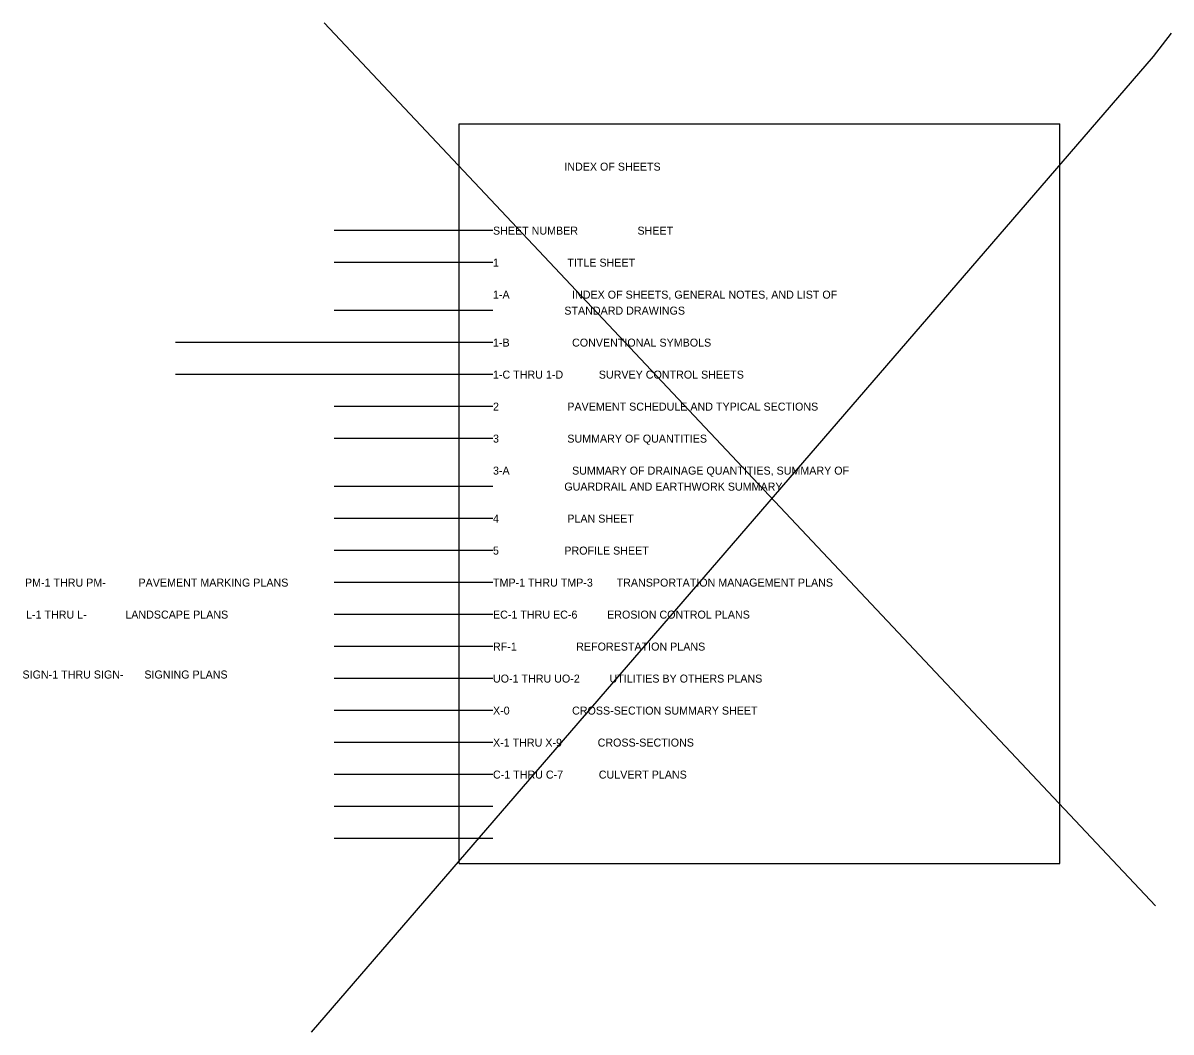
# Model space of a CAD drawing. Extents: x 573885.1 to 573944.9, y -53259.7 to -53181.6.
# Drawn here: x 573885.07 to 573899.41, y -53198.45 to -53185.84 of the extents above; entities that cross this region are included whole.
import ezdxf

# ---------------------------------------------------------------- set-up
doc = ezdxf.new("R2010")
doc.units = 0
for name, color, linetype in [('Scratch_Level_0', 7, 'Continuous'), ('Sheet Data Text CELL', 7, 'Continuous'), ('Sheet Summary Combination Grid CELL', 7, 'Continuous')]:
    doc.layers.add(name, color=color, linetype=linetype)

msp = doc.modelspace()

# ---------------------------------------------------------------- linework, layer by layer
at = {"layer": 'Scratch_Level_0'}
for p, q in [((573890.94, -53188.434), (573888.957, -53188.434)), ((573890.94, -53188.834), (573888.957, -53188.834)), ((573890.94, -53189.434), (573888.957, -53189.434)), ((573888.957, -53189.834), (573886.973, -53189.834)), ((573890.94, -53189.834), (573888.957, -53189.834)), ((573888.957, -53190.234), (573886.973, -53190.234)), ((573888.957, -53190.234), (573886.973, -53190.234)), ((573890.94, -53190.234), (573888.957, -53190.234)), ((573890.94, -53190.234), (573888.957, -53190.234)), ((573890.94, -53190.634), (573888.957, -53190.634)), ((573890.94, -53191.034), (573888.957, -53191.034)), ((573890.94, -53191.634), (573888.957, -53191.634)), ((573890.94, -53191.634), (573888.957, -53191.634)), ((573890.94, -53192.034), (573888.957, -53192.034)), ((573890.94, -53192.434), (573888.957, -53192.434)), ((573890.94, -53192.834), (573888.957, -53192.834)), ((573890.94, -53193.234), (573888.957, -53193.234)), ((573890.94, -53193.634), (573888.957, -53193.634)), ((573890.94, -53194.034), (573888.957, -53194.034)), ((573890.94, -53194.434), (573888.957, -53194.434)), ((573890.94, -53194.834), (573888.957, -53194.834)), ((573890.94, -53195.234), (573888.957, -53195.234)), ((573890.94, -53195.634), (573888.957, -53195.634)), ((573890.94, -53196.034), (573888.957, -53196.034))]:
    msp.add_line(p, q, dxfattribs=at)
at = {"layer": 'Sheet Data Text CELL'}
for p, q in [((573890.518, -53196.344), (573890.518, -53187.099)), ((573890.518, -53187.099), (573898.025, -53187.099)), ((573898.025, -53196.344), (573898.025, -53187.099)), ((573890.518, -53196.344), (573898.025, -53196.344))]:
    msp.add_line(p, q, dxfattribs=at)
at = {"layer": 'Sheet Summary Combination Grid CELL'}
for p, q in [((573888.83, -53185.838), (573899.221, -53196.876)), ((573899.414, -53185.967), (573899.189, -53186.256)), ((573899.189, -53186.256), (573888.669, -53198.453))]:
    msp.add_line(p, q, dxfattribs=at)

# ---------------------------------------------------------------- texts
at = {"layer": 'Sheet Data Text CELL'}
for s, p in [('                        INDEX OF SHEETS ', (573890.94, -53187.684)), ('SHEET NUMBER                    SHEET   ', (573890.94, -53188.484)), ('1                       TITLE SHEET', (573890.94, -53188.884)), ('1-A                     INDEX OF SHEETS, GENERAL NOTES, AND LIST OF ', (573890.94, -53189.284)), ('                        STANDARD DRAWINGS', (573890.94, -53189.484)), ('1-B                     CONVENTIONAL SYMBOLS ', (573890.94, -53189.884)), ('1-C THRU 1-D            SURVEY CONTROL SHEETS', (573890.94, -53190.284)), ('2                       PAVEMENT SCHEDULE AND TYPICAL SECTIONS', (573890.94, -53190.684)), ('3                       SUMMARY OF QUANTITIES ', (573890.94, -53191.084)), ('3-A                     SUMMARY OF DRAINAGE QUANTITIES, SUMMARY OF', (573890.94, -53191.484)), ('                        GUARDRAIL AND EARTHWORK SUMMARY ', (573890.94, -53191.684)), ('4                       PLAN SHEET', (573890.94, -53192.084)), ('5', (573890.94, -53192.484)), ('                        PROFILE SHEET  ', (573890.94, -53192.484)), ('PM-1 THRU PM-           PAVEMENT MARKING PLANS', (573885.091, -53192.884)), ('TMP-1 THRU TMP-3        TRANSPORTATION MANAGEMENT PLANS', (573890.94, -53192.884)), ('L-1 THRU L-             LANDSCAPE PLANS', (573885.104, -53193.284)), ('EC-1 THRU EC-6          EROSION CONTROL PLANS', (573890.94, -53193.284)), ('RF-1                    REFORESTATION PLANS', (573890.94, -53193.684)), ('SIGN-1 THRU SIGN-       SIGNING PLANS', (573885.06, -53194.033)), ('UO-1 THRU UO-2          UTILITIES BY OTHERS PLANS', (573890.94, -53194.084)), ('X-0                     CROSS-SECTION SUMMARY SHEET', (573890.94, -53194.484)), ('X-1 THRU X-9            CROSS-SECTIONS', (573890.94, -53194.884)), ('C-1 THRU C-7            CULVERT PLANS', (573890.94, -53195.284))]:
    msp.add_text(s, height=0.1, dxfattribs=at).set_placement(p)

doc.saveas('drawing.dxf')
